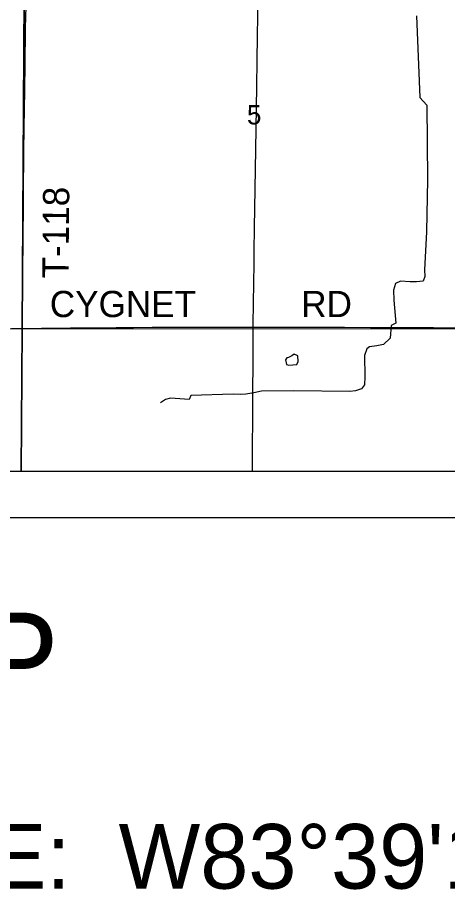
# Model space of a CAD drawing. Extents: x 0 to 39.4, y 0 to 22.
# Drawn here: x 6.358 to 7.289, y 13.194 to 15.083 of the extents above; entities that cross this region are included whole.
import ezdxf

# ---------------------------------------------------------------- set-up
doc = ezdxf.new("R2010")
doc.units = 0
for name, color, linetype in [('Default', 7, 'Continuous'), ('GM_X_County_Road', 7, 'Continuous'), ('GM_X_County_Road_Text', 7, 'Continuous'), ('GM_X_Interstate_Route', 7, 'Continuous'), ('GM_X_Minor_Lake', 7, 'Continuous'), ('GM_X_Minor_River', 7, 'Continuous'), ('GM_X_Section', 7, 'Continuous'), ('GM_X_Section_Text', 7, 'Continuous'), ('GM_X_Township_Road', 7, 'Continuous'), ('GM_X_Township_Road_Text', 7, 'Continuous'), ('SH_Data', 7, 'Continuous'), ('SH_Text', 7, 'Continuous')]:
    doc.layers.add(name, color=color, linetype=linetype)

msp = doc.modelspace()

# ---------------------------------------------------------------- linework, layer by layer
at = {"layer": 'Default'}
for points in [[(5.3634, 14.1), (6.3661, 14.1), (6.3684, 14.4076), (5.3657, 14.4352)], [(6.3661, 14.1), (7.3628, 14.1), (7.3661, 14.4082), (6.3684, 14.4076)]]:
    msp.add_lwpolyline(points, close=True, dxfattribs=at)
at = {"layer": 'GM_X_County_Road'}
for points in [[(6.0522, 14.4139), (6.0876, 14.4134), (6.1249, 14.4126), (6.1808, 14.4118), (6.2398, 14.4103), (6.2522, 14.4099), (6.2833, 14.4086), (6.3082, 14.4085), (6.3455, 14.4089), (6.3686, 14.4093)], [(6.3686, 14.4093), (6.4107, 14.4102), (6.4729, 14.4107), (6.5723, 14.4114), (6.6096, 14.4114), (6.65, 14.4117), (6.7091, 14.412), (6.8178, 14.4123), (6.8675, 14.4122), (6.8685, 14.4122)], [(6.8685, 14.4122), (6.9639, 14.4119), (7.0136, 14.4118), (7.0665, 14.4117), (7.1224, 14.4114), (7.1721, 14.4111), (7.2187, 14.4111), (7.2591, 14.411), (7.3617, 14.4103), (7.4052, 14.4094), (7.4797, 14.4067), (7.6175, 14.4016)]]:
    msp.add_lwpolyline(points, dxfattribs=at)
at = {"layer": 'GM_X_Interstate_Route'}
msp.add_lwpolyline([(5.3699, 15.3511), (5.3635, 14.9304), (5.3615, 14.845), (5.3629, 14.7948), (5.3638, 14.6746), (5.3656, 14.4414), (5.3613, 14.1), (8.9, 14.1), (8.9, 15.3132)], dxfattribs=at)
at = {"layer": 'GM_X_Minor_Lake'}
msp.add_line((6.9451, 14.3465), (6.9413, 14.3454), dxfattribs=at)
msp.add_lwpolyline([(6.9413, 14.3454), (6.9382, 14.3413), (6.9406, 14.331), (6.9455, 14.3294), (6.9633, 14.3312), (6.9658, 14.3376), (6.9649, 14.3502), (6.9574, 14.3538), (6.9524, 14.3497), (6.9451, 14.3465)], dxfattribs=at)
at = {"layer": 'GM_X_Minor_River'}
msp.add_lwpolyline([(7.2219, 15.0865), (7.2291, 14.9098), (7.2445, 14.893), (7.2456, 14.7319), (7.2434, 14.6185), (7.2392, 14.5362), (7.2403, 14.5221), (7.2362, 14.512), (7.2217, 14.5102), (7.2081, 14.5099), (7.1873, 14.5114), (7.1769, 14.5068), (7.1726, 14.4921), (7.173, 14.4705), (7.1771, 14.421), (7.1671, 14.416), (7.1647, 14.388), (7.1509, 14.3744), (7.1361, 14.3719), (7.1201, 14.3698), (7.1143, 14.3654), (7.1092, 14.3508), (7.11, 14.3048), (7.1098, 14.2873), (7.1027, 14.2788), (7.0901, 14.2739), (7.0775, 14.2728), (6.9559, 14.2743), (6.8869, 14.2736), (6.8697, 14.27), (6.8526, 14.2671), (6.8408, 14.266), (6.8249, 14.2669), (6.7335, 14.2643), (6.7297, 14.2553), (6.6893, 14.2582), (6.6786, 14.2555), (6.672, 14.2508), (6.6677, 14.2483)], dxfattribs=at)
at = {"layer": 'GM_X_Section'}
for points in [[(5.3717, 15.3889), (6.3442, 15.3693), (6.3741, 15.3693), (6.3684, 14.4076), (5.3657, 14.4352)], [(6.3741, 15.3693), (7.3525, 15.3518), (7.3801, 15.3507), (7.3661, 14.4082), (6.3684, 14.4076)]]:
    msp.add_lwpolyline(points, close=True, dxfattribs=at)
at = {"layer": 'GM_X_Township_Road'}
for points in [[(6.8685, 14.4122), (6.8685, 14.4182), (6.8698, 14.5084), (6.8705, 14.5488), (6.8708, 14.5757), (6.8716, 14.6282), (6.8722, 14.6692), (6.8742, 14.7967), (6.8762, 14.9336), (6.8771, 14.9895), (6.8777, 15.0424), (6.879, 15.1294), (6.8802, 15.1854), (6.881, 15.2445), (6.8822, 15.3129), (6.883, 15.3409), (6.8837, 15.3533), (6.884, 15.359)], [(6.3686, 14.4093), (6.3687, 14.4174), (6.3689, 14.4329), (6.3692, 14.4485), (6.3699, 14.4888), (6.3701, 14.523), (6.3706, 14.61), (6.3708, 14.6287), (6.3712, 14.6535), (6.3714, 14.6877), (6.3715, 14.7064), (6.3716, 14.7218), (6.3717, 14.7341), (6.3718, 14.7589), (6.3721, 14.7838), (6.3723, 14.8055), (6.3728, 14.8304), (6.3732, 14.8521), (6.3737, 14.8769), (6.3746, 14.9328), (6.3752, 14.9763), (6.3761, 15.0602), (6.377, 15.1069)], [(6.8673, 14.1), (6.8678, 14.2659), (6.8682, 14.3405), (6.8684, 14.3965), (6.8685, 14.4122)]]:
    msp.add_lwpolyline(points, dxfattribs=at)
at = {"layer": 'SH_Data'}
for p, q in [((2.1, 14.1), (8.9, 14.1)), ((2, 14), (9, 14))]:
    msp.add_line(p, q, dxfattribs=at)

# ---------------------------------------------------------------- texts
at = {"layer": 'GM_X_County_Road_Text'}
for s, p in [('CYGNET', (6.4284, 14.4338)), ('RD', (6.9726, 14.4338))]:
    msp.add_text(s, height=0.05682, rotation=0, dxfattribs=at).set_placement(p)
at = {"layer": 'GM_X_Section_Text'}
msp.add_text('5', height=0.0419, rotation=0, dxfattribs=at).set_placement((6.8551, 14.8512))
at = {"layer": 'GM_X_Township_Road_Text'}
msp.add_text('T-118', height=0.05682, rotation=89.4411, dxfattribs=at).set_placement((6.4687, 14.5174))
at = {"layer": 'SH_Text'}
for s, height, p in [('LOCATION MAP', 0.2, (4.4269, 13.5938)), ('LATITUDE:  N41°17\'00"     LONGITUDE:  W83°39\'10"', 0.14, (3.071, 13.1959))]:
    msp.add_text(s, height=height, dxfattribs=at).set_placement(p)

doc.saveas('drawing.dxf')
